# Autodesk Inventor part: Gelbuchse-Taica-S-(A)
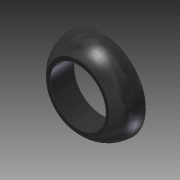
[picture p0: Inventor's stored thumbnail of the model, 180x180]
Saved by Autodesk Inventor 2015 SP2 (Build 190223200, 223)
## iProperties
Created: 2014-11
Part Number: Gelbuchse-Taica-S-(A)
Material: Gummi, Silikon
Document SubType Name: Modeling
Designer: Hübner
Density: 1.25 g/cm^3
Appearance: Gummi - schwarz - Version 1.1
Mass: 0.158091 g
Surface Area: 2.43224 cm^2
Volume: 0.126473 cm^3
Author: Hübner
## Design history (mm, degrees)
sketch "Skizze1"
  geometry: C1 r 3.5 at (0, 0); C2 r 5.5 at (0, 0); 1 further point
  constraints: 2 centre point, 2 coincident
  dimensions: "d0" = 7 diameter of C1; "d1" = 11 diameter of C2
extrude "Extrusion2" new body sketch "Skizze1" distance "d4" = 3; taper "d5" = 0 deg
sketch "Skizze2"
  geometry: L1 (0, 5.5)-(0, -5.5) reference; L2 (0, 5.5)-(-3, 5.5) reference; L3 (-3, 5.5)-(-3, -5.5) reference; L4 (-3.812, 0)-(0.635, 0) reference; A1 r 3.75 centre (0, 1.75) between (0, 5.5) and (-3, 4); 1 further point
  constraints: 2 point on circle, 2 point on line, 1 centre point, 1 end point
  dimensions: "d19" = 4 distance from line of L4 A1.end
revolve "Umdrehung1" sketch "Skizze2" stored, may be unused: angle "d18" = 90 deg
node "Volumenkörper1"
